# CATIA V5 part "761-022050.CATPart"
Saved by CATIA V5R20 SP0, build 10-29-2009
Part number: 761-022050
Source: Unknown
Property "ARTICLENO": "761-022050"
Property "BOMINFO": "761-022050"
Property "CODE": "761-022050"
Property "H": "22.000"
Property "L1": "50.000"
Property "L2": "32.000"
Property "LINA": "761-022050"
Property "NB": "761-022050"
Property "NBSYN": "$CODE."
Property "NN": "761"
Property "NT": "VW/AUDI Keys"
Property "P": "4.000"
Property "SUPPLIER": "CF"
Bounding box of the stored display mesh (mm): x -25 to 25, y 0 to 22, z -11 to 11
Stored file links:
  C:\Users\Utente\Desktop\3D files 761\761-022050.CATPart
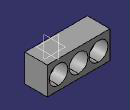
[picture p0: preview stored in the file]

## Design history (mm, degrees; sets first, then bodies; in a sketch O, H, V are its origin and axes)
Body1 "Geometry.1" (main body)
  Solid1 "761-022050.catpart": solid without history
